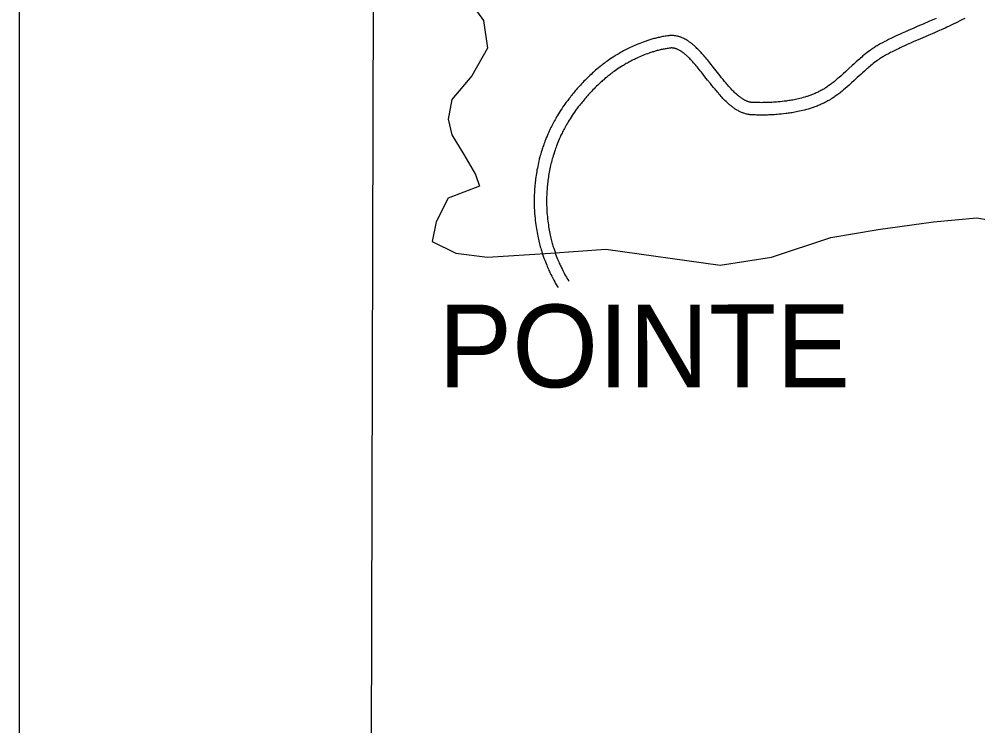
# Model space of a CAD drawing. Extents: x 3177185 to 3215018, y 812988 to 838321.
# Drawn here: x 3180518 to 3182836, y 824865 to 826573 of the extents above; entities that cross this region are included whole.
import ezdxf

# ---------------------------------------------------------------- set-up
doc = ezdxf.new("R2010")
doc.units = 0
for name, color, linetype in [('V-ANNO-SYMB', 7, 'Continuous'), ('V-GRID-FRAM', 7, 'Continuous'), ('V-ROAD-CNTR', 7, 'Continuous'), ('V-SITE-VEGE', 7, 'Continuous'), ('V-TOPO-GNAM-IDEN', 7, 'Continuous'), ('V-TOPO-SHOR', 7, 'Continuous')]:
    doc.layers.add(name, color=color, linetype=linetype)

msp = doc.modelspace()

# ---------------------------------------------------------------- linework, layer by layer
at = {"layer": 'V-ANNO-SYMB'}
msp.add_lwpolyline([(3180518.1, 814196), (3213601.3, 814196), (3213601.3, 837112.6), (3180518.1, 837112.6), (3180518.1, 814196)], dxfattribs=at)
at = {"layer": 'V-GRID-FRAM'}
msp.add_lwpolyline([(3181402.4, 836586.1), (3212801.6, 836513), (3212767.2, 818326.1), (3181352.2, 818399.3), (3181402.4, 836586.1)], dxfattribs=at)
at = {"layer": 'V-ROAD-CNTR'}
for points in [[(3182735, 826575.2), (3182726.6, 826571.5), (3182718.7, 826568.1), (3182703.7, 826561.6), (3182690.6, 826556), (3182679.1, 826551), (3182669.1, 826546.6), (3182660.3, 826542.7), (3182652.6, 826539.3), (3182645.9, 826536.2), (3182640, 826533.5), (3182634.9, 826531.1), (3182630.4, 826529), (3182626.5, 826527.1), (3182619.7, 826523.8), (3182614.6, 826521.2), (3182610.8, 826519.3), (3182605.1, 826516.3), (3182599.5, 826513.3), (3182597, 826511.9), (3182594.5, 826510.5), (3182592.2, 826509.1), (3182589.8, 826507.7), (3182587.6, 826506.3), (3182585.4, 826504.9), (3182583.2, 826503.5), (3182581.1, 826502.1), (3182579.1, 826500.7), (3182577.1, 826499.3), (3182575.1, 826497.9), (3182571.4, 826495.1), (3182567.8, 826492.4), (3182564.3, 826489.7), (3182561, 826487), (3182557.8, 826484.4), (3182554.8, 826481.8), (3182551.9, 826479.4), (3182549.1, 826476.9), (3182546.4, 826474.6), (3182541.3, 826470)], [(3182804, 826575.3), (3182798.1, 826572.2), (3182792.3, 826569.2), (3182786.7, 826566.4), (3182781.3, 826563.7), (3182776, 826561.1), (3182770.9, 826558.7), (3182765.9, 826556.3), (3182761, 826554.1), (3182756.3, 826551.9), (3182747.2, 826547.8), (3182738.7, 826544.1), (3182730.6, 826540.5), (3182715.6, 826534.1), (3182702.5, 826528.4), (3182691.1, 826523.5), (3182681.1, 826519.1), (3182672.5, 826515.3), (3182664.9, 826512), (3182658.4, 826509), (3182652.7, 826506.3), (3182647.7, 826504), (3182643.4, 826502), (3182639.6, 826500.1), (3182633.1, 826496.9), (3182628.2, 826494.5), (3182624.6, 826492.6), (3182619.2, 826489.8), (3182613.8, 826486.9), (3182611.7, 826485.7), (3182609.6, 826484.5), (3182607.5, 826483.3), (3182605.6, 826482.1), (3182603.6, 826480.9), (3182601.7, 826479.7), (3182599.8, 826478.5), (3182598, 826477.3), (3182596.2, 826476), (3182594.4, 826474.8), (3182592.7, 826473.6), (3182589.3, 826471.1), (3182586.1, 826468.6), (3182582.9, 826466.1), (3182579.9, 826463.7), (3182577, 826461.3), (3182574.2, 826459), (3182571.5, 826456.6), (3182568.8, 826454.3), (3182566.3, 826452.1), (3182561.3, 826447.6)], [(3182112.3, 826531.3), (3182111, 826531.7), (3182109.6, 826532), (3182108.3, 826532.3), (3182105.9, 826532.8), (3182103.8, 826533.1), (3182101.9, 826533.4), (3182100.2, 826533.5), (3182098.7, 826533.6), (3182097.4, 826533.7), (3182095.2, 826533.7), (3182093.5, 826533.7), (3182092.1, 826533.6), (3182090.2, 826533.5), (3182088.4, 826533.3), (3182085.4, 826532.9), (3182082.5, 826532.5), (3182079.6, 826532), (3182076.8, 826531.6), (3182074, 826531.1), (3182071.2, 826530.5), (3182068.4, 826530), (3182065.7, 826529.4), (3182063.1, 826528.8), (3182060.4, 826528.2), (3182057.8, 826527.6), (3182055.2, 826526.9), (3182052.7, 826526.2), (3182050.1, 826525.5), (3182047.6, 826524.8), (3182045.2, 826524.1), (3182042.8, 826523.4), (3182040.4, 826522.7), (3182038, 826521.9), (3182035.7, 826521.2), (3182033.4, 826520.4), (3182031.1, 826519.6), (3182026.7, 826518), (3182022.3, 826516.4), (3182018.1, 826514.8), (3182014, 826513.1), (3182010, 826511.5), (3182006.2, 826509.8), (3182002.4, 826508.1), (3181998.8, 826506.5), (3181995.3, 826504.8), (3181991.9, 826503.1), (3181988.6, 826501.5), (3181985.4, 826499.9), (3181982.3, 826498.2), (3181979.3, 826496.6), (3181976.4, 826495), (3181973.6, 826493.5), (3181970.9, 826491.9), (3181968.2, 826490.4), (3181965.7, 826488.9), (3181963.2, 826487.4), (3181960.8, 826485.9), (3181958.5, 826484.5), (3181954.1, 826481.6), (3181949.9, 826478.9), (3181946, 826476.3), (3181942.3, 826473.7), (3181938.9, 826471.3), (3181935.7, 826469), (3181932.8, 826466.8), (3181930, 826464.7), (3181927.4, 826462.7), (3181925, 826460.8), (3181922.7, 826459), (3181918.5, 826455.6), (3181914.8, 826452.5), (3181911.6, 826449.8), (3181908.8, 826447.3), (3181906.3, 826445.2), (3181904.2, 826443.2), (3181900.5, 826439.9), (3181897.8, 826437.3), (3181895.7, 826435.3), (3181892.7, 826432.3), (3181889.6, 826429.3), (3181886.5, 826426.2), (3181883.5, 826423.1), (3181880.6, 826420), (3181877.8, 826417), (3181875.1, 826414.1), (3181872.5, 826411.2)], [(3182281.2, 826373.6), (3182279.9, 826374.1), (3182278.7, 826374.5), (3182277.5, 826374.9), (3182276.3, 826375.4), (3182275.2, 826375.9), (3182274, 826376.5), (3182272.8, 826377.1), (3182271.7, 826377.7), (3182270.5, 826378.3), (3182269.3, 826379), (3182268.1, 826379.7), (3182267, 826380.4), (3182265.8, 826381.2), (3182264.6, 826382), (3182263.5, 826382.8), (3182262.3, 826383.6), (3182261.2, 826384.4), (3182260, 826385.3), (3182258.9, 826386.2), (3182257.7, 826387.1), (3182256.6, 826388.1), (3182255.4, 826389), (3182254.3, 826389.9), (3182252.1, 826391.9), (3182249.8, 826394), (3182247.6, 826396.1), (3182245.5, 826398.2), (3182243.3, 826400.3), (3182241.2, 826402.5), (3182239.1, 826404.8), (3182237.1, 826407), (3182235, 826409.2), (3182233, 826411.5), (3182231, 826413.7), (3182229.1, 826416), (3182227.2, 826418.3), (3182225.3, 826420.5), (3182223.4, 826422.8), (3182219.7, 826427.3), (3182216.2, 826431.7), (3182212.7, 826436.1), (3182205.9, 826444.7), (3182199.6, 826452.8), (3182193.6, 826460.4), (3182190.8, 826464), (3182188, 826467.4), (3182185.4, 826470.7), (3182182.8, 826473.9), (3182180.3, 826476.9), (3182177.8, 826479.8), (3182175.4, 826482.6), (3182173.1, 826485.3), (3182170.8, 826487.9), (3182168.6, 826490.3), (3182166.5, 826492.7), (3182164.4, 826494.9), (3182162.4, 826497), (3182160.4, 826499.1), (3182158.5, 826501), (3182156.6, 826502.8), (3182154.8, 826504.6), (3182153, 826506.3), (3182151.2, 826507.8), (3182149.5, 826509.3), (3182147.9, 826510.8), (3182146.3, 826512.1), (3182144.7, 826513.4), (3182143.2, 826514.6), (3182141.7, 826515.8), (3182140.2, 826516.9), (3182138.8, 826517.9), (3182137.4, 826518.9), (3182136, 826519.8), (3182134.7, 826520.7), (3182133.4, 826521.6), (3182132.1, 826522.4), (3182129.7, 826523.8), (3182127.3, 826525.1), (3182125.1, 826526.3), (3182123, 826527.3), (3182121, 826528.2), (3182119.1, 826529), (3182117.3, 826529.7), (3182115.6, 826530.3), (3182114, 826530.8), (3182112.6, 826531.2)], [(3182104.3, 826502.4), (3182103.3, 826502.7), (3182102.6, 826502.8), (3182102, 826503), (3182100.6, 826503.3), (3182099.5, 826503.4), (3182098.6, 826503.6), (3182097.7, 826503.6), (3182097, 826503.7), (3182096.5, 826503.7), (3182095.3, 826503.7), (3182094.5, 826503.7), (3182093.9, 826503.7), (3182092.9, 826503.6), (3182091.9, 826503.5), (3182089.4, 826503.2), (3182086.9, 826502.8), (3182084.4, 826502.4), (3182081.9, 826502), (3182079.4, 826501.6), (3182077, 826501.1), (3182074.5, 826500.6), (3182072.1, 826500.1), (3182069.7, 826499.6), (3182067.4, 826499), (3182065, 826498.4), (3182062.7, 826497.9), (3182060.4, 826497.3), (3182058.2, 826496.6), (3182055.9, 826496), (3182053.7, 826495.4), (3182051.5, 826494.7), (3182049.4, 826494), (3182047.2, 826493.4), (3182045.1, 826492.7), (3182043, 826492), (3182041, 826491.3), (3182036.9, 826489.8), (3182033, 826488.4), (3182029.1, 826486.9), (3182025.4, 826485.4), (3182021.8, 826483.8), (3182018.2, 826482.3), (3182014.8, 826480.8), (3182011.5, 826479.3), (3182008.3, 826477.7), (3182005.2, 826476.2), (3182002.1, 826474.7), (3181999.2, 826473.2), (3181996.4, 826471.7), (3181993.6, 826470.2), (3181990.9, 826468.8), (3181988.3, 826467.3), (3181985.8, 826465.9), (3181983.4, 826464.5), (3181981.1, 826463.1), (3181978.8, 826461.7), (3181976.6, 826460.4), (3181974.5, 826459.1), (3181970.4, 826456.4), (3181966.5, 826453.9), (3181962.9, 826451.5), (3181959.6, 826449.2), (3181956.4, 826446.9), (3181953.5, 826444.8), (3181950.7, 826442.8), (3181948.2, 826440.8), (3181945.8, 826439), (3181943.5, 826437.2), (3181941.5, 826435.6), (3181937.5, 826432.4), (3181934.1, 826429.6), (3181931.2, 826427), (3181928.6, 826424.8), (3181926.3, 826422.8), (3181924.4, 826421.1), (3181921, 826417.9), (3181918.4, 826415.5), (3181916.6, 826413.7), (3181913.7, 826411), (3181910.9, 826408.2), (3181908, 826405.2), (3181905.2, 826402.3), (3181902.4, 826399.4), (3181899.7, 826396.6), (3181897.1, 826393.8), (3181894.6, 826391)], [(3182271.9, 826345.1), (3182270.2, 826345.7), (3182268.3, 826346.3), (3182266.4, 826347.1), (3182264.5, 826347.8), (3182262.7, 826348.6), (3182260.9, 826349.5), (3182259.2, 826350.3), (3182257.5, 826351.2), (3182255.8, 826352.2), (3182254.1, 826353.1), (3182252.5, 826354.1), (3182250.9, 826355.1), (3182249.3, 826356.1), (3182247.7, 826357.2), (3182246.2, 826358.2), (3182244.7, 826359.3), (3182243.2, 826360.4), (3182241.7, 826361.5), (3182240.3, 826362.6), (3182238.9, 826363.8), (3182237.5, 826364.9), (3182236.1, 826366.1), (3182234.7, 826367.3), (3182232, 826369.6), (3182229.4, 826372), (3182226.8, 826374.5), (3182224.3, 826376.9), (3182221.9, 826379.4), (3182219.5, 826381.8), (3182217.2, 826384.3), (3182214.9, 826386.7), (3182212.7, 826389.2), (3182210.5, 826391.6), (3182208.4, 826394.1), (3182206.3, 826396.5), (3182204.3, 826398.9), (3182202.2, 826401.3), (3182200.3, 826403.7), (3182196.4, 826408.4), (3182192.7, 826413), (3182189.2, 826417.5), (3182182.3, 826426.1), (3182176, 826434.3), (3182170.1, 826441.8), (3182167.3, 826445.3), (3182164.6, 826448.6), (3182162.1, 826451.8), (3182159.6, 826454.8), (3182157.2, 826457.7), (3182154.9, 826460.5), (3182152.7, 826463.1), (3182150.5, 826465.6), (3182148.4, 826468), (3182146.4, 826470.2), (3182144.5, 826472.3), (3182142.6, 826474.3), (3182140.8, 826476.2), (3182139, 826478), (3182137.3, 826479.7), (3182135.7, 826481.3), (3182134.2, 826482.8), (3182132.6, 826484.2), (3182131.2, 826485.5), (3182129.8, 826486.8), (3182128.4, 826487.9), (3182127.1, 826489), (3182125.9, 826490.1), (3182124.7, 826491), (3182123.5, 826491.9), (3182122.4, 826492.8), (3182121.3, 826493.5), (3182120.2, 826494.3), (3182119.2, 826495), (3182118.3, 826495.6), (3182117.4, 826496.2), (3182116.5, 826496.7), (3182114.7, 826497.8), (3182113.2, 826498.7), (3182111.7, 826499.4), (3182110.3, 826500.1), (3182109.1, 826500.6), (3182107.9, 826501.1), (3182106.9, 826501.5), (3182105.9, 826501.9), (3182105, 826502.2), (3182103.9, 826502.5)], [(3182541.2, 826469.9), (3182536.5, 826465.6), (3182532, 826461.5), (3182523.8, 826453.9), (3182516.6, 826447.2), (3182510.3, 826441.5), (3182504.9, 826436.5), (3182500, 826432.3), (3182495.8, 826428.7), (3182492.1, 826425.6), (3182488.8, 826422.9), (3182485.9, 826420.6), (3182483.4, 826418.6), (3182481.1, 826416.9), (3182479.2, 826415.5), (3182475.7, 826412.9), (3182473.1, 826411.1), (3182471.2, 826409.7), (3182468.2, 826407.7), (3182465.2, 826405.8), (3182462.9, 826404.4), (3182460.6, 826403), (3182458.3, 826401.7), (3182456, 826400.5), (3182453.7, 826399.3), (3182451.5, 826398.1), (3182449.2, 826397), (3182447, 826395.9), (3182444.7, 826394.9), (3182442.5, 826393.9), (3182440.3, 826393), (3182438.1, 826392.1), (3182435.9, 826391.2), (3182433.7, 826390.3), (3182431.6, 826389.5), (3182429.4, 826388.8), (3182427.3, 826388), (3182425.2, 826387.3), (3182423.2, 826386.6), (3182421.2, 826386), (3182417.1, 826384.7), (3182413.1, 826383.6), (3182409.2, 826382.6), (3182405.4, 826381.6), (3182401.7, 826380.7), (3182398.1, 826379.9), (3182394.7, 826379.2), (3182391.3, 826378.5), (3182388, 826377.8), (3182384.8, 826377.3), (3182381.6, 826376.7), (3182378.6, 826376.3), (3182375.7, 826375.8), (3182372.9, 826375.4), (3182370.1, 826375), (3182367.5, 826374.7), (3182362.3, 826374.1), (3182357.5, 826373.6), (3182353, 826373.2), (3182348.8, 826372.8), (3182344.9, 826372.5), (3182341.3, 826372.3), (3182337.9, 826372.1), (3182334.7, 826371.9), (3182331.7, 826371.8), (3182329, 826371.7), (3182326.4, 826371.6), (3182324, 826371.6), (3182319.6, 826371.5), (3182315.7, 826371.5), (3182312.4, 826371.4), (3182309.5, 826371.5), (3182307.1, 826371.5), (3182304.9, 826371.5), (3182301.1, 826371.6), (3182298.4, 826371.7), (3182296.4, 826371.7), (3182293.3, 826371.8), (3182290.5, 826372), (3182289.2, 826372.1), (3182288, 826372.2), (3182286.8, 826372.3), (3182285.7, 826372.5), (3182284.5, 826372.8), (3182283.3, 826373), (3182282.2, 826373.3), (3182280.8, 826373.7)], [(3182561.4, 826447.7), (3182556.7, 826443.5), (3182552.4, 826439.5), (3182544.2, 826431.9), (3182536.9, 826425.1), (3182530.5, 826419.3), (3182524.8, 826414.1), (3182519.7, 826409.7), (3182515.2, 826405.8), (3182511.2, 826402.4), (3182507.6, 826399.5), (3182504.5, 826397), (3182501.7, 826394.8), (3182499.2, 826393), (3182497, 826391.3), (3182493.2, 826388.5), (3182490.2, 826386.4), (3182488, 826384.9), (3182484.6, 826382.6), (3182481.2, 826380.4), (3182478.4, 826378.7), (3182475.7, 826377.1), (3182473, 826375.5), (3182470.3, 826374.1), (3182467.6, 826372.6), (3182464.9, 826371.3), (3182462.3, 826370), (3182459.6, 826368.7), (3182457, 826367.5), (3182454.4, 826366.4), (3182451.9, 826365.3), (3182449.4, 826364.3), (3182446.9, 826363.3), (3182444.4, 826362.3), (3182441.9, 826361.4), (3182439.5, 826360.5), (3182437.1, 826359.7), (3182434.8, 826358.9), (3182432.4, 826358.1), (3182430.1, 826357.4), (3182425.6, 826356), (3182421.1, 826354.7), (3182416.8, 826353.5), (3182412.6, 826352.5), (3182408.5, 826351.5), (3182404.6, 826350.6), (3182400.8, 826349.8), (3182397, 826349), (3182393.4, 826348.4), (3182389.9, 826347.7), (3182386.6, 826347.1), (3182383.3, 826346.6), (3182380.1, 826346.1), (3182377, 826345.7), (3182374.1, 826345.3), (3182371.2, 826344.9), (3182365.7, 826344.3), (3182360.5, 826343.7), (3182355.7, 826343.3), (3182351.2, 826342.9), (3182347, 826342.6), (3182343.1, 826342.3), (3182339.5, 826342.1), (3182336.1, 826342), (3182332.9, 826341.8), (3182330, 826341.7), (3182327.3, 826341.6), (3182324.7, 826341.6), (3182320, 826341.5), (3182315.9, 826341.5), (3182312.4, 826341.4), (3182309.3, 826341.5), (3182306.7, 826341.5), (3182304.4, 826341.5), (3182300.4, 826341.6), (3182297.5, 826341.7), (3182295.3, 826341.8), (3182292.1, 826341.9), (3182288.8, 826342), (3182286.7, 826342.2), (3182284.5, 826342.4), (3182282.4, 826342.7), (3182280.3, 826343), (3182278.2, 826343.4), (3182276.1, 826343.9), (3182274.1, 826344.4), (3182272.3, 826345)], [(3181872.4, 826411.1), (3181869.8, 826408.3), (3181867.3, 826405.5), (3181864.9, 826402.7), (3181862.5, 826400), (3181860.2, 826397.3), (3181858, 826394.6), (3181855.8, 826392), (3181853.7, 826389.4), (3181851.7, 826386.8), (3181849.7, 826384.3), (3181847.8, 826381.8), (3181845.9, 826379.4), (3181844.1, 826377), (3181842.3, 826374.6), (3181840.6, 826372.3), (3181838.9, 826370), (3181835.7, 826365.5), (3181832.6, 826361), (3181829.7, 826356.8), (3181827, 826352.6), (3181824.4, 826348.6), (3181821.9, 826344.6), (3181819.6, 826340.8), (3181817.4, 826337.1), (3181815.3, 826333.5), (3181813.4, 826330.1), (3181811.5, 826326.7), (3181809.7, 826323.4), (3181808, 826320.2), (3181806.4, 826317.1), (3181804.9, 826314.1), (3181803.5, 826311.2), (3181802.1, 826308.4), (3181800.8, 826305.6), (3181799.5, 826302.9), (3181798.3, 826300.3), (3181796.1, 826295.3), (3181794.1, 826290.6), (3181792.3, 826286.1), (3181790.6, 826281.9), (3181789.1, 826278), (3181787.7, 826274.3), (3181786.5, 826270.8), (3181785.3, 826267.5), (3181784.3, 826264.5), (3181783.3, 826261.6), (3181781.6, 826256.1), (3181780.1, 826251.4), (3181778.9, 826247.2), (3181777.9, 826243.5), (3181777, 826240.2), (3181775.5, 826234.6), (3181774.5, 826230.3), (3181773.7, 826227.1), (3181772.6, 826222.3), (3181771.6, 826217.4), (3181770.7, 826213), (3181769.8, 826208.7), (3181769.1, 826204.4), (3181768.4, 826200.1), (3181767.7, 826195.9), (3181767.1, 826191.7), (3181766.5, 826187.6), (3181766, 826183.6), (3181765.6, 826179.5), (3181765.1, 826175.6), (3181764.8, 826171.7), (3181764.4, 826167.8), (3181764.1, 826164), (3181763.9, 826160.2), (3181763.7, 826156.5), (3181763.5, 826152.8), (3181763.3, 826149.2), (3181763.2, 826145.7), (3181763.1, 826142.2), (3181763.1, 826138.7), (3181763, 826135.3), (3181763, 826131.9), (3181763.1, 826128.6), (3181763.1, 826125.3), (3181763.2, 826122.1), (3181763.3, 826118.9), (3181763.4, 826115.8), (3181763.6, 826112.7), (3181763.7, 826109.7), (3181763.9, 826106.8)], [(3181894.7, 826391.1), (3181892.2, 826388.3), (3181889.8, 826385.7), (3181887.6, 826383), (3181885.3, 826380.5), (3181883.2, 826377.9), (3181881.1, 826375.4), (3181879, 826373), (3181877.1, 826370.5), (3181875.2, 826368.1), (3181873.3, 826365.8), (3181871.5, 826363.5), (3181869.7, 826361.2), (3181868, 826359), (3181866.4, 826356.7), (3181864.8, 826354.6), (3181863.2, 826352.4), (3181860.2, 826348.2), (3181857.4, 826344.1), (3181854.7, 826340.1), (3181852.1, 826336.3), (3181849.7, 826332.5), (3181847.5, 826328.9), (3181845.3, 826325.4), (3181843.3, 826321.9), (3181841.4, 826318.6), (3181839.5, 826315.4), (3181837.8, 826312.3), (3181836.2, 826309.2), (3181834.6, 826306.3), (3181833.1, 826303.4), (3181831.7, 826300.7), (3181830.4, 826298), (3181829.1, 826295.4), (3181827.9, 826292.8), (3181826.8, 826290.4), (3181825.7, 826288), (3181823.6, 826283.4), (3181821.8, 826279), (3181820.1, 826274.9), (3181818.6, 826271), (3181817.2, 826267.4), (3181815.9, 826264), (3181814.7, 826260.8), (3181813.7, 826257.8), (3181812.7, 826254.9), (3181811.8, 826252.3), (3181810.2, 826247.2), (3181808.9, 826242.8), (3181807.8, 826238.9), (3181806.8, 826235.5), (3181806, 826232.5), (3181804.6, 826227.2), (3181803.6, 826223.3), (3181802.9, 826220.3), (3181801.9, 826215.8), (3181800.9, 826211.3), (3181800.1, 826207.2), (3181799.3, 826203.2), (3181798.6, 826199.2), (3181798, 826195.3), (3181797.4, 826191.4), (3181796.8, 826187.5), (3181796.3, 826183.7), (3181795.8, 826180), (3181795.4, 826176.2), (3181795, 826172.6), (3181794.6, 826168.9), (3181794.3, 826165.4), (3181794.1, 826161.8), (3181793.8, 826158.3), (3181793.6, 826154.9), (3181793.4, 826151.5), (3181793.3, 826148.1), (3181793.2, 826144.8), (3181793.1, 826141.6), (3181793.1, 826138.3), (3181793, 826135.2), (3181793, 826132), (3181793.1, 826129), (3181793.1, 826125.9), (3181793.2, 826122.9), (3181793.3, 826120), (3181793.4, 826117.1), (3181793.5, 826114.2), (3181793.7, 826111.4), (3181793.9, 826108.6)], [(3181763.9, 826106.6), (3181764.1, 826103.7), (3181764.6, 826098), (3181765.1, 826092.3), (3181765.7, 826086.9), (3181766.3, 826081.6), (3181766.9, 826076.5), (3181767.7, 826071.5), (3181768.4, 826066.8), (3181769.2, 826062.1), (3181770, 826057.6), (3181770.8, 826053.3), (3181771.7, 826049.1), (3181772.5, 826045), (3181773.4, 826041.1), (3181774.3, 826037.3), (3181775.2, 826033.6), (3181776.1, 826030), (3181777, 826026.6), (3181777.9, 826023.2), (3181778.8, 826020), (3181779.7, 826016.9), (3181780.6, 826013.9), (3181781.5, 826010.9), (3181782.4, 826008.1), (3181783.3, 826005.4), (3181785.1, 826000.1), (3181786.8, 825995.2), (3181788.5, 825990.6), (3181790.1, 825986.3), (3181791.7, 825982.3), (3181793.3, 825978.6), (3181794.7, 825975.1), (3181796.1, 825971.8), (3181797.5, 825968.8), (3181798.8, 825965.9), (3181800, 825963.2), (3181801.2, 825960.7), (3181803.5, 825956.1), (3181805.5, 825952), (3181807.3, 825948.5), (3181809, 825945.4), (3181810.5, 825942.7), (3181813, 825938.1), (3181815, 825934.6), (3181816.6, 825932), (3181818.9, 825928.2), (3181821.3, 825924.4)], [(3181793.8, 826108.7), (3181794, 826105.9), (3181794.5, 826100.5), (3181794.9, 826095.3), (3181795.5, 826090.2), (3181796, 826085.3), (3181796.7, 826080.6), (3181797.3, 826076), (3181798, 826071.5), (3181798.7, 826067.2), (3181799.5, 826063.1), (3181800.3, 826059), (3181801, 826055.2), (3181801.8, 826051.4), (3181802.7, 826047.7), (3181803.5, 826044.2), (3181804.3, 826040.8), (3181805.1, 826037.5), (3181806, 826034.3), (3181806.8, 826031.2), (3181807.7, 826028.3), (3181808.5, 826025.4), (3181809.3, 826022.6), (3181810.2, 826019.9), (3181811, 826017.3), (3181811.8, 826014.8), (3181813.4, 826009.9), (3181815, 826005.4), (3181816.6, 826001.1), (3181818.1, 825997.2), (3181819.6, 825993.5), (3181821, 825990.1), (3181822.3, 825986.8), (3181823.6, 825983.8), (3181824.9, 825981), (3181826.1, 825978.4), (3181827.2, 825976), (3181828.3, 825973.7), (3181830.4, 825969.4), (3181832.2, 825965.7), (3181833.9, 825962.5), (3181835.4, 825959.6), (3181836.7, 825957.2), (3181839.1, 825952.9), (3181841, 825949.7), (3181842.3, 825947.4), (3181844.5, 825943.8), (3181846.7, 825940.3)]]:
    msp.add_lwpolyline(points, dxfattribs=at)
at = {"layer": 'V-SITE-VEGE'}
msp.add_line((3181362.2, 822024.4), (3181380.6, 828682.7), dxfattribs=at)
at = {"layer": 'V-TOPO-SHOR'}
msp.add_lwpolyline([(3181593, 826636.9), (3181640.7, 826570.1), (3181650.2, 826503.4), (3181612.1, 826436.6), (3181564.4, 826379.4), (3181554.8, 826331.7), (3181564.4, 826293.6), (3181593, 826245.9), (3181621.6, 826198.2), (3181631.1, 826169.6), (3181554.8, 826140.9), (3181526.2, 826083.7), (3181516.7, 826036), (3181573.9, 826007.4), (3181650.2, 825997.9), (3181802.8, 826007.4), (3181936.3, 826017), (3182212.9, 825978.8), (3182336.9, 825997.9), (3182480, 826045.6), (3182594.4, 826064.6), (3182728, 826083.7), (3182832.9, 826093.3), (3182937.8, 826074.2)], dxfattribs=at)

# ---------------------------------------------------------------- texts
at = {"layer": 'V-TOPO-GNAM-IDEN'}
msp.add_text('POINTE', height=200, rotation=0.0278, dxfattribs=at).set_placement((3181531.4, 825683.2))

doc.saveas('drawing.dxf')
